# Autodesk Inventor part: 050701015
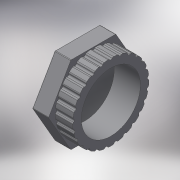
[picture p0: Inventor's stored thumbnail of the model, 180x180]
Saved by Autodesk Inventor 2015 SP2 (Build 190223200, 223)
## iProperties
Created: 2017-10
Part Number: 050701015
Material: Generic
Description: PLASSON THREADED CAP PVC 1.1/2"
Document SubType Name: Modeling
Designer: KIM
Density: 1 g/cm^3
Appearance: Default
Author: KIM
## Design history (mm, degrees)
derived "050701.ipt"
feature "Solid1::050701.ipt"
tag "TaggingFeature1"
body "Solid1"
other parameters: "d0" = 38, "d1" = 56.84, "d2" = 1, "d3" = 12, "d4" = 58, "d5" = 24, "d6" = 44.845, "d7" = 7.2, "d10" = 0, "d11" = 2.32, "d13" = 0, "d14" = 1.16, "d16" = 360 deg, "d18" = 0.58, "G_" = 44.845, "C_" = 58, "B_" = 12, "Lt_" = 24, "H_" = 38
